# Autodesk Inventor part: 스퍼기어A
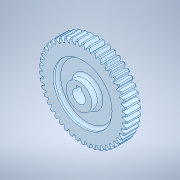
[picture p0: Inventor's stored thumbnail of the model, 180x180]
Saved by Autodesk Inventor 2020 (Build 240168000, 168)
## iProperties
Created: 2024-05
Part Number: 스퍼기어A
Material: 강철, 탄소
Document SubType Name: Modeling
Designer: oem
Density: 7.85 g/cm^3
Appearance: 기본값
Author: jhkim
Sending System: Autodesk Inventor 2025
Preprocessor: ST-DEVELOPER v20
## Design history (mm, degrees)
node "스퍼기어A1"
node "솔리드2"
node "솔리드1"
